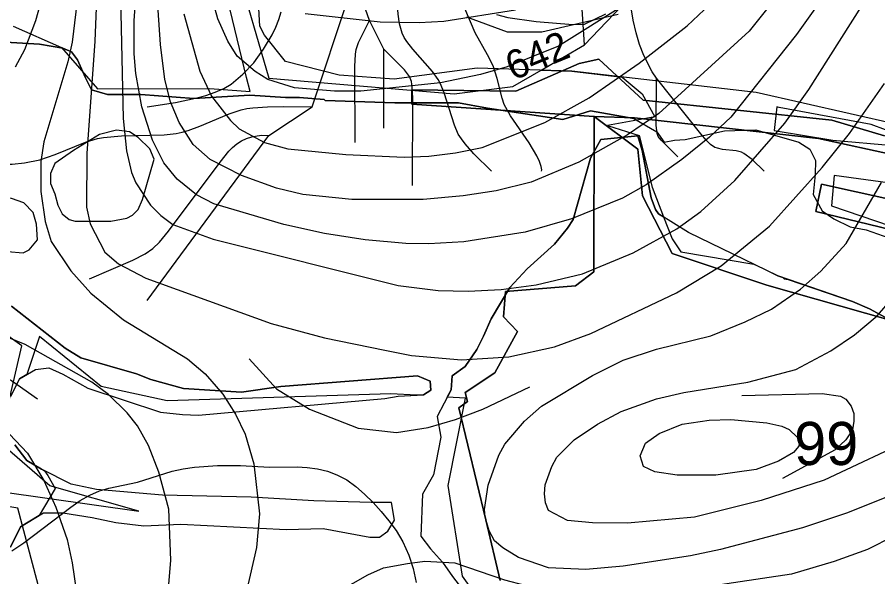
# Model space of a CAD drawing. Extents: x -709584 to -702006, y -1161789 to -1157496.
# Drawn here: x -707759.7 to -707459.8, y -1160645.8 to -1160450.8 of the extents above; entities that cross this region are included whole.
import ezdxf

# ---------------------------------------------------------------- set-up
doc = ezdxf.new("R2010")
doc.units = 0
for name, color, linetype in [('102_obvod PÚ', 7, 'Continuous'), ('120_vrstevnice hlavní', 7, 'Continuous'), ('121_vrstevnice hlavní_popis', 7, 'Continuous'), ('122_vrstevnice základní', 7, 'Continuous'), ('124_vrstevnice doplňková', 7, 'Continuous'), ('408_BPEJ_linie', 7, 'Continuous'), ('409_BPEJ_popis', 7, 'Continuous'), ('411_akumulovaný odtok', 7, 'Continuous'), ('419_LPIS PB', 7, 'Continuous')]:
    doc.layers.add(name, color=color, linetype=linetype)

msp = doc.modelspace()

# ---------------------------------------------------------------- linework, layer by layer
at = {"layer": '102_obvod PÚ'}
for points in [[(-707761.13, -1160453.89), (-707744.29, -1160461.35), (-707731.77, -1160475.83), (-707692.56, -1160475.65), (-707678.57, -1160476.69), (-707679.78, -1160471.77), (-707686.29, -1160444.92)], [(-707603.21, -1160450.64), (-707588.96, -1160455.87), (-707576.9, -1160455.94), (-707550.32, -1160449.73)], [(-707622.18, -1160481.06), (-707622.18, -1160476.13), (-707585.97, -1160476.6), (-707563.88, -1160466.89), (-707557.03, -1160465.43), (-707541.65, -1160479.74), (-707475.88, -1160486.71), (-707457.47, -1160492.14)], [(-707457.47, -1160492.14), (-707475.88, -1160486.71), (-707541.65, -1160479.74), (-707557.03, -1160465.43), (-707563.88, -1160466.89), (-707585.97, -1160476.6), (-707622.18, -1160476.13), (-707622.18, -1160481.06)], [(-707452.69, -1160499.06), (-707480.52, -1160493.06), (-707544.67, -1160485.93), (-707558.65, -1160485.36), (-707622.18, -1160481.06)], [(-707622.18, -1160481.06), (-707558.65, -1160485.36), (-707558.76, -1160539.48), (-707565.18, -1160544.41), (-707589.59, -1160546.4), (-707590.3, -1160555.25), (-707585.38, -1160560.25), (-707593.3, -1160574.66), (-707603.58, -1160581.51), (-707602.86, -1160584.72), (-707605.79, -1160586.94), (-707596.43, -1160625.87), (-707591.47, -1160647.06)], [(-707605.79, -1160586.94), (-707602.86, -1160584.72), (-707603.58, -1160581.51), (-707593.3, -1160574.66), (-707585.38, -1160560.25), (-707590.3, -1160555.25), (-707589.59, -1160546.4), (-707565.18, -1160544.41), (-707558.76, -1160539.48), (-707558.65, -1160485.36), (-707543.49, -1160496.74), (-707541.85, -1160513.01), (-707531.5, -1160533.13), (-707498.53, -1160544.12), (-707455.58, -1160556.39), (-707449.94, -1160569.95), (-707390.14, -1160584.87), (-707367.3, -1160590.65), (-707332.53, -1160607.76), (-707328.88, -1160612.34), (-707349.5, -1160617.62), (-707372.91, -1160652.8)], [(-707455.58, -1160556.39), (-707498.53, -1160544.12), (-707531.5, -1160533.13), (-707541.85, -1160513.01), (-707543.49, -1160496.74), (-707558.65, -1160485.36), (-707544.67, -1160485.93), (-707480.52, -1160493.06), (-707452.69, -1160499.06)], [(-707425.85, -1160531.95), (-707481.44, -1160518.54), (-707479.45, -1160508.98), (-707455.25, -1160514.33)], [(-707455.25, -1160514.33), (-707479.45, -1160508.98), (-707481.44, -1160518.54), (-707425.85, -1160531.95)], [(-707781.32, -1160613.88), (-707717.33, -1160622.85), (-707748.33, -1160614.04), (-707765.99, -1160598.87), (-707758.16, -1160565.25), (-707791, -1160541.97)], [(-707591.47, -1160647.06), (-707596.43, -1160625.87), (-707605.79, -1160586.94)], [(-707751.86, -1160650.79), (-707759.55, -1160621.87), (-707783.74, -1160617.73)]]:
    msp.add_lwpolyline(points, dxfattribs=at)
at = {"layer": '120_vrstevnice hlavní'}
for points in [[(-707778.81, -1160218.5), (-707758.13, -1160278.68), (-707751.33, -1160301.24), (-707746.41, -1160323.8), (-707743.37, -1160335.09), (-707730.21, -1160376.46), (-707726.3, -1160395.26), (-707724.28, -1160417.82), (-707722.83, -1160486.09), (-707721.68, -1160497.38), (-707719.94, -1160504.9), (-707718.35, -1160508.52), (-707713.29, -1160516.32), (-707709.67, -1160519.94), (-707705.48, -1160522.98), (-707691.45, -1160528.19), (-707626.93, -1160544.24), (-707613.05, -1160545.98), (-707602.63, -1160546.27), (-707591.06, -1160545.69), (-707578.91, -1160544.1)], [(-707578.91, -1160544.1), (-707562.71, -1160540.19), (-707545.07, -1160532.96), (-707529.88, -1160524.57), (-707521.49, -1160518.5), (-707509.63, -1160507.65), (-707492.27, -1160487.69), (-707483.88, -1160475.97), (-707465.51, -1160447.04), (-707460.59, -1160440.24), (-707431.81, -1160408.42)], [(-707659.33, -1160449.5), (-707633.3, -1160452.39), (-707619.7, -1160452.68), (-707611.02, -1160452.25), (-707586.14, -1160448.2)]]:
    msp.add_lwpolyline(points, dxfattribs=at)
at = {"layer": '122_vrstevnice základní'}
for points in [[(-707822.78, -1160181.04), (-707813.67, -1160190.01), (-707804.7, -1160201.72), (-707801.23, -1160207.51), (-707789.37, -1160230.65), (-707780.11, -1160253.8), (-707774.76, -1160271.15), (-707766.08, -1160299.5), (-707762.9, -1160309.92), (-707744.09, -1160385.42), (-707743.08, -1160393.23), (-707739.34, -1160424.32), (-707738.45, -1160442.12), (-707740.62, -1160459.48), (-707742.07, -1160466.42), (-707750.46, -1160494.2), (-707751.47, -1160501.14), (-707751.47, -1160511.55), (-707750.03, -1160521.97), (-707747.86, -1160528.91), (-707741.06, -1160539.18), (-707734.11, -1160546.99), (-707722.69, -1160556.25), (-707700.41, -1160569.84)], [(-707761.31, -1160289.67), (-707755.38, -1160310.79), (-707745.25, -1160355.05), (-707738.89, -1160373.27), (-707734.26, -1160388.89), (-707731.8, -1160401.91), (-707730.79, -1160412.33), (-707732.67, -1160459.19), (-707735.42, -1160498.25), (-707735.56, -1160517.05), (-707734.26, -1160522.83), (-707729.2, -1160532.67), (-707724.42, -1160536.72), (-707714.88, -1160541.78), (-707671.2, -1160557.55), (-707652.68, -1160562.47), (-707631.62, -1160566.85), (-707622.31, -1160568.69), (-707604.95, -1160570.13), (-707588.46, -1160569.12)], [(-707760.3, -1160468.16), (-707757.11, -1160462.08), (-707753.21, -1160451.96), (-707750.46, -1160441.83), (-707748.72, -1160423.61), (-707748.29, -1160404.37), (-707754.08, -1160375.01), (-707759.43, -1160355.92), (-707768.69, -1160317.73)], [(-707701.71, -1160449.65), (-707696.07, -1160469.61), (-707692.02, -1160478.28), (-707685.37, -1160486.82), (-707682.33, -1160489.71), (-707673.51, -1160494.48), (-707665.41, -1160496.65), (-707645.16, -1160498.68), (-707624.91, -1160499.55), (-707616.23, -1160499.26), (-707606.97, -1160498.1), (-707597.71, -1160496.22), (-707575.87, -1160487.54), (-707560.4, -1160478.86), (-707543.04, -1160466.86), (-707526.26, -1160453.84), (-707504.58, -1160433.29), (-707492.48, -1160420.08), (-707487.79, -1160414.35), (-707479.98, -1160403.94), (-707474.91, -1160396.13), (-707462.47, -1160377.03), (-707461.32, -1160375.3), (-707456.92, -1160369.1)], [(-707491.26, -1160438.8), (-707504.71, -1160455.72), (-707536.1, -1160484.36), (-707547.09, -1160491.74), (-707564.01, -1160501.28), (-707580.65, -1160508.23), (-707592.8, -1160511.26), (-707604.37, -1160513), (-707618.26, -1160514.3), (-707643.13, -1160514.3), (-707660.2, -1160512.56), (-707669.31, -1160510.4), (-707681.61, -1160505.91), (-707692.46, -1160500.42), (-707698.39, -1160495.21), (-707703.31, -1160487.54), (-707706.34, -1160480.31), (-707708.22, -1160472.5), (-707709.81, -1160460.35), (-707712.85, -1160415.8)], [(-707547.52, -1160446.17), (-707571.1, -1160460.93), (-707589.04, -1160468.16), (-707598.29, -1160470.76), (-707612.18, -1160473.66), (-707639.95, -1160476.55), (-707649.21, -1160476.55), (-707663.09, -1160475.39), (-707672.35, -1160472.5), (-707676.84, -1160469.75), (-707683.06, -1160464.4), (-707686.38, -1160459.19), (-707689.85, -1160451.38), (-707697.66, -1160422.74)], [(-707471.15, -1160432.86), (-707488.22, -1160456.88), (-707511.07, -1160485.66), (-707518.45, -1160492.6), (-707528.14, -1160500.41), (-707540.58, -1160509.24), (-707548.83, -1160513.87), (-707566.62, -1160521.1), (-707582.67, -1160525.73), (-707604.08, -1160529.05), (-707616.23, -1160529.78), (-707624.33, -1160529.63), (-707638.51, -1160528.33), (-707652.68, -1160526.16), (-707666.85, -1160522.98), (-707691.16, -1160515.89), (-707697.23, -1160512.71), (-707704.03, -1160507.21), (-707708.66, -1160501.57), (-707712.56, -1160493.62), (-707716.32, -1160482.04), (-707718.35, -1160470.47), (-707718.93, -1160463.53), (-707718.93, -1160451.96), (-707717.77, -1160435.76)], [(-707588.46, -1160569.12), (-707572.55, -1160565.65), (-707559.82, -1160561.02), (-707530.02, -1160546.85), (-707514.4, -1160537.44), (-707497.62, -1160523.56), (-707479.25, -1160503.16), (-707469.7, -1160491.3), (-707457.56, -1160473.95)], [(-707433.4, -1160608.61), (-707470.43, -1160623.51), (-707486.05, -1160628.71), (-707514.69, -1160636.24), (-707525.1, -1160638.41), (-707548.54, -1160642.02), (-707561.55, -1160643.18), (-707574.57, -1160642.6), (-707584.99, -1160638.98), (-707590.48, -1160635.66), (-707593.38, -1160633.2), (-707595.26, -1160629.73), (-707596.7, -1160624.95), (-707596.85, -1160622.35), (-707595.59, -1160613.79), (-707591.93, -1160603.4), (-707589.76, -1160599.5), (-707582.96, -1160591.54), (-707577.03, -1160586.33), (-707559.24, -1160575.63), (-707548.54, -1160570.28), (-707536.96, -1160566.52), (-707518.01, -1160561.82), (-707506.01, -1160556.97), (-707496.9, -1160552.49), (-707486.77, -1160545.54), (-707479.69, -1160539.32), (-707470.86, -1160529.63), (-707458.57, -1160508.37)], [(-707445.84, -1160596.75), (-707478.53, -1160612.08), (-707500.51, -1160619.17), (-707523.66, -1160624.95), (-707547.09, -1160627.04), (-707559.24, -1160626.98), (-707567.92, -1160626.11), (-707574.57, -1160622.64), (-707575.58, -1160620.04), (-707576.02, -1160616.85), (-707575.73, -1160613.67), (-707573.42, -1160607.31), (-707571.68, -1160604.12), (-707565.6, -1160598.05), (-707557.5, -1160592.55), (-707549.26, -1160588.21), (-707536.96, -1160583.73), (-707527.42, -1160581.56), (-707505.14, -1160577.94), (-707488.36, -1160573.6), (-707476.21, -1160567.1), (-707467.97, -1160561.46), (-707460.01, -1160554.8), (-707453.07, -1160546.85)], [(-707733.68, -1160577.94), (-707756.97, -1160564.78), (-707763.19, -1160562.32)], [(-707700.41, -1160569.84), (-707694.19, -1160575.05), (-707688.12, -1160582.14), (-707683.63, -1160589.08), (-707680.31, -1160596.03), (-707677.27, -1160606.44), (-707675.32, -1160623.86), (-707676.33, -1160635.6), (-707683.63, -1160667.48)], [(-708051.9, -1160649.4), (-708036.57, -1160638.84), (-708027.6, -1160633.78), (-708000.12, -1160620.76), (-707943.71, -1160591.54), (-707933.29, -1160588.21), (-707915.07, -1160583.44), (-707899.44, -1160580.69), (-707881.22, -1160579.1), (-707857.79, -1160578.23), (-707841.3, -1160578.67), (-707806.87, -1160580.98), (-707788.65, -1160584.31), (-707778.52, -1160586.91), (-707772.45, -1160589.23), (-707764.49, -1160593.86), (-707756.1, -1160602.68), (-707750.46, -1160612.23), (-707746.27, -1160621.48), (-707742.36, -1160632.76), (-707740.62, -1160640.86), (-707737.88, -1160659.09)], [(-707707.65, -1160658.22), (-707706.2, -1160640), (-707706.92, -1160622.21), (-707710.39, -1160609.33), (-707714.01, -1160600.07), (-707717.77, -1160593.13), (-707721.39, -1160588.65), (-707727.9, -1160582.28), (-707733.68, -1160577.94)], [(-707489.17, -1160602.51), (-707494.46, -1160605.44), (-707502.27, -1160608.38), (-707516.33, -1160610.41), (-707529.73, -1160610.34), (-707537.54, -1160609.19), (-707541.45, -1160607.31), (-707542.6, -1160603.65), (-707540.84, -1160599.24), (-707536.05, -1160595.82), (-707527.98, -1160592.64), (-707518.65, -1160591.17), (-707511.09, -1160590.93), (-707498.49, -1160592.12), (-707493.28, -1160593.28), (-707490.68, -1160594.43), (-707487.91, -1160597.12), (-707487.16, -1160597.95), (-707487.4, -1160600.3), (-707489.17, -1160602.51)], [(-707454.23, -1160631.61), (-707463.48, -1160636.24), (-707475.06, -1160640.43), (-707489.93, -1160644.83), (-707542.75, -1160652.73)]]:
    msp.add_lwpolyline(points, dxfattribs=at)
at = {"layer": '124_vrstevnice doplňková'}
for points in [[(-707870.02, -1160567.12), (-707849.09, -1160563.2), (-707831.46, -1160561.89), (-707818.44, -1160562.47), (-707804.85, -1160564.06), (-707790.96, -1160566.66), (-707771.14, -1160573.03), (-707761.74, -1160577.36), (-707752.63, -1160583.73)], [(-707678.89, -1160569.79), (-707669.31, -1160580.26), (-707657.89, -1160587.35), (-707640.96, -1160594), (-707627.51, -1160595.45), (-707616.52, -1160593.71), (-707606.97, -1160590.96), (-707597.43, -1160587.35), (-707581.08, -1160579.53)], [(-707507.17, -1160582.64), (-707479.19, -1160581.91), (-707472.89, -1160582.89), (-707470.99, -1160583.88), (-707469.11, -1160586.31), (-707468.22, -1160588.93), (-707468.22, -1160591.51), (-707468.66, -1160594.52), (-707470.99, -1160598.06), (-707474.66, -1160601.48), (-707493.06, -1160611.51)], [(-707677.79, -1160673.12), (-707665.43, -1160661.87), (-707652.83, -1160653.74), (-707637.49, -1160645.06), (-707632.12, -1160642.63), (-707623.75, -1160641.15), (-707617.68, -1160640.29), (-707607.26, -1160640.86), (-707589.9, -1160646.79), (-707582.82, -1160648.68)]]:
    msp.add_lwpolyline(points, dxfattribs=at)
at = {"layer": '408_BPEJ_linie'}
msp.add_line((-707577.12, -1160469.27), (-707562, -1160460.5), dxfattribs=at)
for points in [[(-707562, -1160460.5), (-707564, -1160430), (-707574, -1160398.5), (-707576, -1160371.5), (-707559.5, -1160326.5), (-707556.5, -1160295), (-707565, -1160254.5), (-707568, -1160244), (-707576, -1160227.5), (-707583, -1160212), (-707590, -1160204), (-707592.5, -1160191.5), (-707589, -1160173.5), (-707577, -1160126), (-707575.5, -1160115), (-707576.5, -1160092.5), (-707582, -1160078)], [(-707562, -1160460.5), (-707544, -1160441.5), (-707510, -1160362.5)], [(-707683.5, -1160432.5), (-707672, -1160472), (-707607.5, -1160477.5), (-707587, -1160475), (-707577.12, -1160469.27)], [(-707543.84, -1160486.65), (-707544.8, -1160486.1), (-707559.9, -1160483.4), (-707569.6, -1160486.4), (-707595.8, -1160482.5), (-707606, -1160480.7), (-707628.1, -1160480.7), (-707652.38, -1160479.81), (-707652.7, -1160479.5), (-707661.3, -1160478.8), (-707666.2, -1160478.8), (-707678.6, -1160478), (-707698.12, -1160479.16), (-707716.6, -1160477.8), (-707728.3, -1160477.8), (-707733.8, -1160476.1), (-707735.9, -1160471.9), (-707738.7, -1160465.7), (-707740.8, -1160462.9), (-707743.8, -1160461.6), (-707751.9, -1160460.2), (-707777.9, -1160458.7)], [(-707577.12, -1160469.27), (-707566.5, -1160469.6), (-707548.88, -1160471.66), (-707542, -1160477.5), (-707537.5, -1160485.5), (-707543.84, -1160486.65)], [(-707452.2, -1160491.91), (-707462.11, -1160488.21), (-707494.21, -1160482.23), (-707495.01, -1160482.08), (-707495.98, -1160490.34), (-707475.53, -1160493.64), (-707454.45, -1160495.56)], [(-707543.84, -1160486.65), (-707554, -1160488.5), (-707543, -1160492), (-707538.5, -1160510), (-707534.46, -1160520.39)], [(-707595.2, -1160658.71), (-707604.5, -1160645.5), (-707609.5, -1160614), (-707603.5, -1160583.5), (-707609.84, -1160583.13), (-707608.5, -1160580.6), (-707608.2, -1160575.7), (-707603.6, -1160572.5), (-707599.5, -1160566.6), (-707597.2, -1160561.9), (-707594.6, -1160555.9), (-707588.01, -1160544.95), (-707582, -1160538.42), (-707572.49, -1160529.88), (-707567.98, -1160524.36), (-707565.98, -1160521.34), (-707559.9, -1160499.9), (-707556.3, -1160493.4), (-707543.4, -1160492.1), (-707541.9, -1160497.3), (-707538.77, -1160513.75), (-707537.27, -1160517.76), (-707536.27, -1160519.27), (-707534.46, -1160520.39)], [(-707453, -1160509), (-707475, -1160506), (-707476, -1160516.5), (-707455.5, -1160523.5)], [(-707534.46, -1160520.39), (-707531.5, -1160528), (-707528.5, -1160532.5), (-707503.09, -1160536.8), (-707500, -1160538.3), (-707494.72, -1160540.86), (-707492.96, -1160541.47), (-707492.5, -1160542), (-707491.05, -1160542.14), (-707468.7, -1160549.9), (-707462.69, -1160552.41), (-707457.18, -1160555.43), (-707450.43, -1160559.81), (-707445.5, -1160570), (-707437.5, -1160574), (-707412, -1160581), (-707388, -1160587), (-707340.5, -1160603), (-707332, -1160609.5), (-707345.5, -1160618), (-707357, -1160635), (-707369, -1160645), (-707369.5, -1160650.5)], [(-707761.69, -1160551.47), (-707743, -1160566.1), (-707737.5, -1160569.5), (-707718.2, -1160575.1), (-707713.1, -1160577), (-707701.8, -1160580.2), (-707681.6, -1160581.4), (-707667.9, -1160579.5), (-707620.2, -1160575.8), (-707615.8, -1160577.6), (-707615.6, -1160580.7), (-707618.1, -1160582.4), (-707620.61, -1160582.51), (-707629.5, -1160582), (-707707.5, -1160584.5), (-707730.5, -1160579.5), (-707752, -1160562), (-707756.37, -1160575.33), (-707758.9, -1160576.8), (-707761.9, -1160582.8)], [(-707760.6, -1160599.8), (-707756.4, -1160605.3), (-707751.2, -1160608.3), (-707750.24, -1160608.79), (-707749, -1160610.5), (-707746.5, -1160615), (-707752.1, -1160624.45), (-707758.6, -1160628.3), (-707762.1, -1160635.4)]]:
    msp.add_lwpolyline(points, dxfattribs=at)
at = {"layer": '411_akumulovaný odtok'}
for p, q in [((-707656.99, -1160482), (-707641.99, -1160437)), ((-707636.99, -1160452), (-707641.99, -1160437)), ((-707631.99, -1160462), (-707636.99, -1160452)), ((-707631.99, -1160489.5), (-707631.99, -1160462)), ((-707671.99, -1160492), (-707656.99, -1160482)), ((-707714.49, -1160549.5), (-707671.99, -1160492))]:
    msp.add_line(p, q, dxfattribs=at)
for points in [[(-707576.99, -1160504.5), (-707576.88, -1160504.01), (-707577.1, -1160502.82), (-707577.68, -1160501.12), (-707578.61, -1160499.16), (-707581.36, -1160494.62), (-707587.84, -1160485.17), (-707589.99, -1160481.18), (-707590.76, -1160479), (-707592.47, -1160472.21), (-707593.87, -1160467.78), (-707595.84, -1160463.89), (-707600.18, -1160456.26), (-707603.75, -1160447.74), (-707604.96, -1160445.67), (-707607.86, -1160441.73), (-707616.02, -1160432.26), (-707618.94, -1160428.32), (-707620.16, -1160426.24), (-707621.12, -1160424.13), (-707623.59, -1160417.49), (-707626.29, -1160412.34), (-707631.58, -1160404.3), (-707636.99, -1160397)], [(-707594.49, -1160504.5), (-707600.6, -1160498.43), (-707603.63, -1160494.96), (-707604.95, -1160493.2), (-707606.02, -1160491.51), (-707607.39, -1160488.42), (-707610.98, -1160477.12), (-707612.24, -1160474.03), (-707613.01, -1160472.56), (-707614.95, -1160469.74), (-707621.83, -1160461.92), (-707623.93, -1160459.26), (-707624.83, -1160457.86), (-707625.57, -1160456.4), (-707626.52, -1160453.16), (-707626.98, -1160449.72), (-707627.7, -1160440.89), (-707628.17, -1160438.96), (-707628.95, -1160436.97), (-707630, -1160435.06), (-707632.57, -1160431.55), (-707635.09, -1160428.8), (-707636.99, -1160427)], [(-707536.99, -1160472), (-707538.49, -1160469.9), (-707541.38, -1160464.19), (-707542.86, -1160460.37), (-707544.09, -1160456.25), (-707545.07, -1160451.9), (-707545.81, -1160447.52)], [(-707714.49, -1160482), (-707704.61, -1160480.49), (-707697.57, -1160479.05), (-707694.03, -1160478.1), (-707690.69, -1160476.99), (-707687.71, -1160475.68), (-707685.22, -1160474.19), (-707681.04, -1160470.72), (-707677.3, -1160466.7), (-707673.84, -1160461.98), (-707670.89, -1160456.95), (-707669.65, -1160454.33), (-707668.59, -1160451.65), (-707667.76, -1160448.9)], [(-707641.99, -1160494.5), (-707642.03, -1160467.98), (-707641.88, -1160463.74), (-707641.63, -1160462.09), (-707640.84, -1160459.69), (-707636.99, -1160452)], [(-707621.99, -1160509.5), (-707621.9, -1160479.06), (-707622.06, -1160475.08), (-707622.38, -1160473.18), (-707623.06, -1160471.44), (-707624.75, -1160469.1), (-707631.99, -1160462)], [(-707529.49, -1160499.5), (-707535.37, -1160493.69), (-707536.35, -1160492.33), (-707536.76, -1160491.3), (-707537.04, -1160488.39), (-707536.99, -1160472)], [(-707499.49, -1160504.5), (-707503.66, -1160500.36), (-707506.49, -1160498.26), (-707507.35, -1160497.86), (-707509.17, -1160497.42), (-707513.94, -1160496.9), (-707515.75, -1160496.5), (-707516.59, -1160496.16), (-707518.15, -1160495.12), (-707519.56, -1160493.76), (-707521.55, -1160491.46), (-707536.99, -1160472)], [(-707764.49, -1160502), (-707761.49, -1160502), (-707757.16, -1160501.57), (-707751.85, -1160500.47), (-707746.46, -1160498.69), (-707735.91, -1160494.31), (-707731.74, -1160493.07), (-707729.68, -1160492.69), (-707723.38, -1160492.16), (-707708.48, -1160491.74), (-707704.3, -1160491.28), (-707702.25, -1160490.89), (-707700.15, -1160490.31), (-707696.03, -1160488.82), (-707685.87, -1160484.48), (-707681.73, -1160483.11), (-707679.75, -1160482.67), (-707677.63, -1160482.36), (-707672.55, -1160482), (-707667.06, -1160481.89), (-707656.99, -1160482)], [(-707734.49, -1160542), (-707719.39, -1160535.48), (-707715.09, -1160533.2), (-707712.48, -1160531.39), (-707710.13, -1160529.16), (-707706.95, -1160525.38), (-707689.01, -1160501.29), (-707685.93, -1160497.43), (-707684.71, -1160496.17), (-707683.24, -1160494.96), (-707681.59, -1160493.88), (-707679.8, -1160493.03), (-707677.94, -1160492.46), (-707676.14, -1160492.13), (-707674.52, -1160491.97), (-707671.99, -1160492)], [(-707761.57, -1160636.75), (-707757.4, -1160633.88), (-707741.04, -1160621.5), (-707737.73, -1160619.2), (-707734.46, -1160617.29), (-707731.08, -1160615.81), (-707727.82, -1160614.86), (-707717.78, -1160612.79), (-707705.76, -1160608.99), (-707701.91, -1160608.17), (-707697.95, -1160607.61), (-707689.9, -1160607.03), (-707681.89, -1160607.01), (-707671.84, -1160607.54), (-707662.19, -1160607.47), (-707658.64, -1160607.71), (-707655.1, -1160608.2), (-707651.64, -1160608.99), (-707648.31, -1160610.19), (-707644.91, -1160612.02), (-707641.7, -1160614.32), (-707638.65, -1160616.97), (-707635.73, -1160619.88), (-707632.92, -1160622.99), (-707630.25, -1160626.26), (-707627.72, -1160629.68), (-707625.36, -1160633.55), (-707623.27, -1160638.17), (-707621.75, -1160642.85), (-707620.65, -1160647.77)]]:
    msp.add_lwpolyline(points, dxfattribs=at)
at = {"layer": '419_LPIS PB'}
for points in [[(-707403.9, -1160499.3), (-707502.24, -1160477.09), (-707566.5, -1160469.6), (-707599.48, -1160468.57), (-707628.4, -1160472.4), (-707647.5, -1160471), (-707666.2, -1160466.3), (-707673.54, -1160457.08), (-707675.2, -1160453.9), (-707675.54, -1160447.76)], [(-707592.7, -1160449.9), (-707588.7, -1160450.9), (-707578.9, -1160452.3), (-707566.1, -1160453.4), (-707562, -1160453.2), (-707554.6, -1160449.7)], [(-707777.9, -1160458.7), (-707751.9, -1160460.2), (-707743.8, -1160461.6), (-707740.8, -1160462.9), (-707738.7, -1160465.7), (-707735.9, -1160471.9), (-707733.8, -1160476.1), (-707728.3, -1160477.8), (-707716.6, -1160477.8), (-707698.12, -1160479.16), (-707678.6, -1160478), (-707666.2, -1160478.8), (-707661.3, -1160478.8), (-707652.7, -1160479.5), (-707652.38, -1160479.81), (-707628.1, -1160480.7), (-707606, -1160480.7), (-707595.8, -1160482.5), (-707569.6, -1160486.4), (-707559.9, -1160483.4), (-707544.8, -1160486.1), (-707536.8, -1160490.7), (-707534.3, -1160494.3), (-707530.7, -1160493.7), (-707527, -1160493.4), (-707513.3, -1160490.4), (-707502.3, -1160490), (-707487.4, -1160494.4), (-707483.5, -1160496.8), (-707481.5, -1160500.7), (-707481.7, -1160505.6), (-707482.4, -1160512.6), (-707479.2, -1160518.3), (-707475.1, -1160521.1), (-707469.5, -1160523.8), (-707463.9, -1160524.9), (-707454, -1160528.4)], [(-707457.18, -1160555.43), (-707462.69, -1160552.41), (-707468.7, -1160549.9), (-707494.72, -1160540.86), (-707525.76, -1160525.8), (-707536.27, -1160519.27), (-707537.27, -1160517.76), (-707538.77, -1160513.75), (-707541.9, -1160497.3), (-707543.4, -1160492.1), (-707556.3, -1160493.4), (-707559.9, -1160499.9), (-707565.98, -1160521.34), (-707567.98, -1160524.36), (-707572.49, -1160529.88), (-707582, -1160538.42), (-707588.01, -1160544.95), (-707594.6, -1160555.9), (-707597.2, -1160561.9), (-707599.5, -1160566.6), (-707603.6, -1160572.5), (-707608.2, -1160575.7), (-707608.5, -1160580.6), (-707613.4, -1160589.9), (-707612.07, -1160597.12), (-707614.6, -1160610.2), (-707618.5, -1160617), (-707619.06, -1160631.58), (-707615.7, -1160636), (-707611.55, -1160640.61), (-707608.04, -1160645.64), (-707601.54, -1160654.17)], [(-707761.9, -1160582.8), (-707758.9, -1160576.8), (-707753.4, -1160573.6), (-707748.7, -1160573), (-707743.8, -1160575.2), (-707735.1, -1160580), (-707709.8, -1160588.4), (-707702.1, -1160589.2), (-707696.5, -1160589.4), (-707631.6, -1160583.6), (-707627, -1160582.8), (-707618.1, -1160582.4), (-707615.6, -1160580.7), (-707615.8, -1160577.6), (-707620.2, -1160575.8), (-707667.9, -1160579.5), (-707681.6, -1160581.4), (-707701.8, -1160580.2), (-707713.1, -1160577), (-707718.2, -1160575.1), (-707737.5, -1160569.5), (-707743, -1160566.1), (-707761.69, -1160551.47)], [(-707762.1, -1160635.4), (-707758.6, -1160628.3), (-707750.5, -1160623.5), (-707743.8, -1160623.5), (-707733.6, -1160625.1), (-707725.4, -1160626.8), (-707715.6, -1160628), (-707702.7, -1160627.4), (-707666, -1160629.3), (-707653.1, -1160628.9), (-707636.9, -1160632), (-707633.5, -1160632), (-707630.6, -1160629.9), (-707628.3, -1160626), (-707629.3, -1160619.9), (-707636.4, -1160619.9), (-707656.3, -1160619.3), (-707678.2, -1160618), (-707709.1, -1160617.3), (-707732.1, -1160615.3), (-707740.9, -1160613.5), (-707751.2, -1160608.3), (-707756.4, -1160605.3), (-707760.6, -1160599.8)]]:
    msp.add_lwpolyline(points, dxfattribs=at)
for points in [[(-707748.09, -1160508.79), (-707746.59, -1160512.3), (-707745.59, -1160516.32), (-707744.09, -1160519.33), (-707741.58, -1160521.34), (-707739.58, -1160521.84), (-707727.07, -1160521.84), (-707721.56, -1160520.84), (-707719.56, -1160519.84), (-707717.56, -1160517.82), (-707716.06, -1160514.31), (-707712.05, -1160500.25), (-707713.55, -1160496.73), (-707717.56, -1160492.72), (-707720.56, -1160490.71), (-707725.07, -1160490.21), (-707731.07, -1160491.71), (-707740.08, -1160497.24), (-707746.59, -1160501.75), (-707748.09, -1160505.27)], [(-707774, -1160528.9), (-707769.8, -1160531.2), (-707763.11, -1160532.39), (-707757.6, -1160532.89), (-707755.6, -1160531.89), (-707752.59, -1160528.37), (-707753, -1160522.9), (-707754.1, -1160518.83), (-707757.4, -1160515.5), (-707761.7, -1160514), (-707765.3, -1160513.8), (-707773, -1160522.1), (-707774.1, -1160525.1)]]:
    msp.add_lwpolyline(points, close=True, dxfattribs=at)

# ---------------------------------------------------------------- texts
at = {"layer": '121_vrstevnice hlavní_popis'}
msp.add_text('642', height=10, rotation=22.2845, dxfattribs=at).set_placement((-707586.96, -1160473))
at = {"layer": '409_BPEJ_popis'}
msp.add_text('99', height=15, dxfattribs=at).set_placement((-707488.98, -1160606.82))

doc.saveas('drawing.dxf')
